// Mitsubishi GX Works2 project: 高速计数中断   PLC: FX3U/FX3UC

PROGRAM MAIN
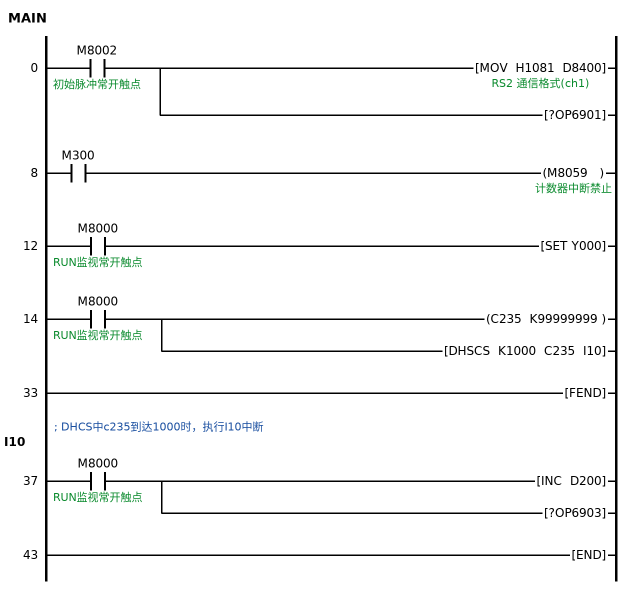
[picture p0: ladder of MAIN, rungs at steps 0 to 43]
0     LD      M8002  ; 初始脉冲常开触点
      MOV     H1081 D8400  ; RS2 通信格式(ch1)
      ?OP6901
        [note] 允许中断
8     LD      M300
      OUT     M8059  ; 计数器中断禁止
        [note] 为NO时，所有计数中断禁止
12    LD      M8000  ; RUN监视常开触点
      SET     Y000
14    LD      M8000  ; RUN监视常开触点
      OUT     C235 K99999999
      DHSCS   K1000 C235 I10
33    FEND
        [note] 主程序结束
      I10
; DHCS中c235到达1000时，执行I10中断
37    LD      M8000  ; RUN监视常开触点
      INC     D200
      ?OP6903
        [note] 中断返回
43    END
END_PROGRAM

// device comments not shown above
C10  ; CCD1拍照连续不良计数
C11  ; CCD2连续不良计数
